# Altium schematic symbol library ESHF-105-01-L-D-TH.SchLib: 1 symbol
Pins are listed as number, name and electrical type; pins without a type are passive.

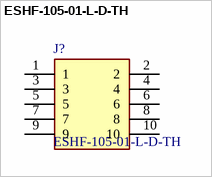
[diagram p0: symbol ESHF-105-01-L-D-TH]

## ESHF-105-01-L-D-TH
designator J?
.050" Shrouded Terminal Strip For FFSD, through hole, dual row,  positions per row; Manufacturer_Name: SAMTEC; Geometry.Height: 5.33mm
footprint ESHF10501LDTH
pins: 1, 2, 3, 4, 5, 6, 7, 8, 9, 10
